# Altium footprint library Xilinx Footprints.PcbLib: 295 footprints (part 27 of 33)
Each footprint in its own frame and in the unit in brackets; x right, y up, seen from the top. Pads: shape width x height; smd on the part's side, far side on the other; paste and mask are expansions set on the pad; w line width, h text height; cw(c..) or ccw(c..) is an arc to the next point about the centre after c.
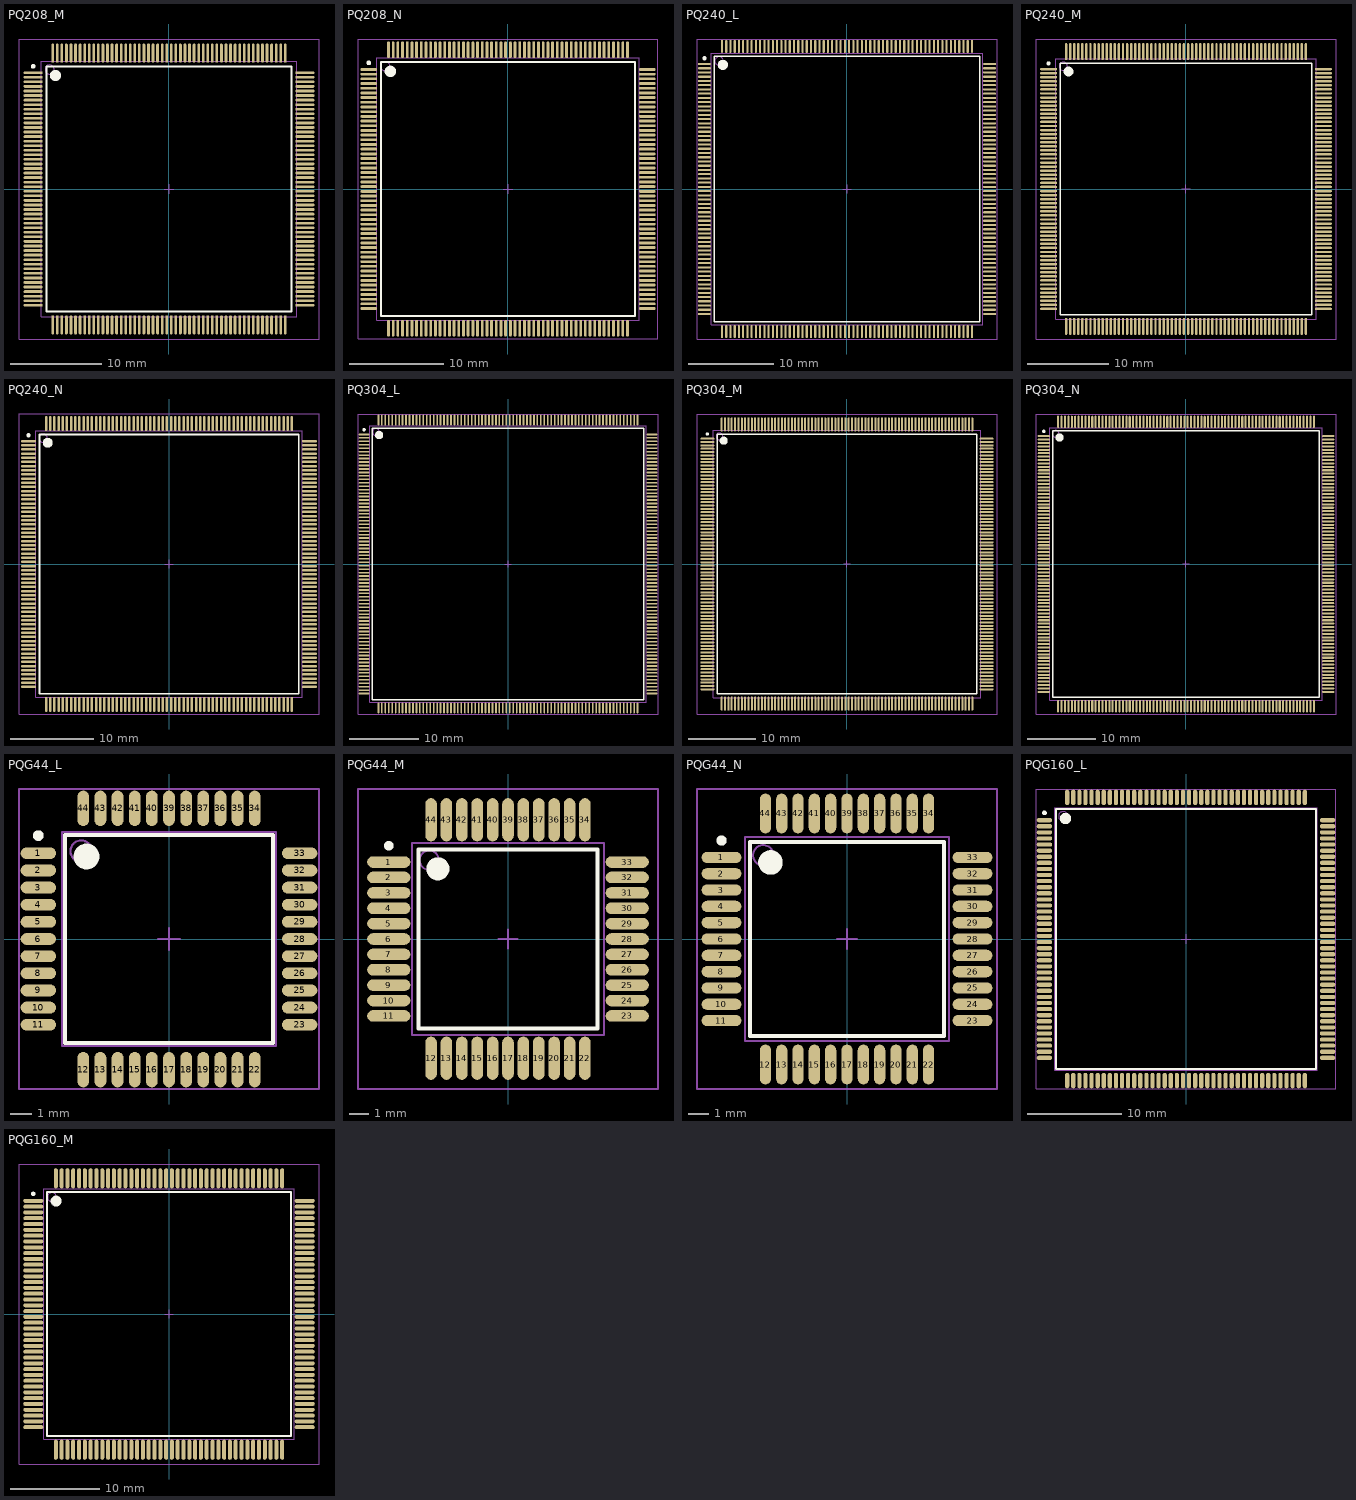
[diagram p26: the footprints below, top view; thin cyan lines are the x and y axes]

## PQ208_M [mm] "208-Pin Plastic Quad Flat Pack (PQ208), IPC Low Density"
height 4.1
pads (208):
  oval 2.1x0.3 smd: 1(-14.9,12.75) 2(-14.9,12.25) 3(-14.9,11.75) 4(-14.9,11.25) 5(-14.9,10.75) 6(-14.9,10.25) 7(-14.9,9.75) 8(-14.9,9.25) 9(-14.9,8.75) 10(-14.9,8.25) 11(-14.9,7.75) 12(-14.9,7.25) 13(-14.9,6.75) 14(-14.9,6.25) 15(-14.9,5.75) 16(-14.9,5.25) 17(-14.9,4.75) 18(-14.9,4.25) 19(-14.9,3.75) 20(-14.9,3.25) 21(-14.9,2.75) 22(-14.9,2.25) 23(-14.9,1.75) 24(-14.9,1.25) 25(-14.9,0.75) 26(-14.9,0.25) 27(-14.9,-0.25) 28(-14.9,-0.75) 29(-14.9,-1.25) 30(-14.9,-1.75) 31(-14.9,-2.25) 32(-14.9,-2.75) 33(-14.9,-3.25) 34(-14.9,-3.75) 35(-14.9,-4.25) 36(-14.9,-4.75) 37(-14.9,-5.25) 38(-14.9,-5.75) 39(-14.9,-6.25) 40(-14.9,-6.75) 41(-14.9,-7.25) 42(-14.9,-7.75) 43(-14.9,-8.25) 44(-14.9,-8.75) 45(-14.9,-9.25) 46(-14.9,-9.75) 47(-14.9,-10.25) 48(-14.9,-10.75) 49(-14.9,-11.25) 50(-14.9,-11.75) 51(-14.9,-12.25) 52(-14.9,-12.75) 105(14.9,-12.75) 106(14.9,-12.25) 107(14.9,-11.75) 108(14.9,-11.25) 109(14.9,-10.75) 110(14.9,-10.25) 111(14.9,-9.75) 112(14.9,-9.25) 113(14.9,-8.75) 114(14.9,-8.25) 115(14.9,-7.75) 116(14.9,-7.25) 117(14.9,-6.75) 118(14.9,-6.25) 119(14.9,-5.75) 120(14.9,-5.25) 121(14.9,-4.75) 122(14.9,-4.25) 123(14.9,-3.75) 124(14.9,-3.25) 125(14.9,-2.75) 126(14.9,-2.25) 127(14.9,-1.75) 128(14.9,-1.25) 129(14.9,-0.75) 130(14.9,-0.25) 131(14.9,0.25) 132(14.9,0.75) 133(14.9,1.25) 134(14.9,1.75) 135(14.9,2.25) 136(14.9,2.75) 137(14.9,3.25) 138(14.9,3.75) 139(14.9,4.25) 140(14.9,4.75) 141(14.9,5.25) 142(14.9,5.75) 143(14.9,6.25) 144(14.9,6.75) 145(14.9,7.25) 146(14.9,7.75) 147(14.9,8.25) 148(14.9,8.75) 149(14.9,9.25) 150(14.9,9.75) 151(14.9,10.25) 152(14.9,10.75) 153(14.9,11.25) 154(14.9,11.75) 155(14.9,12.25) 156(14.9,12.75)
  oval 0.3x2.1 smd: 53(-12.75,-14.9) 54(-12.25,-14.9) 55(-11.75,-14.9) 56(-11.25,-14.9) 57(-10.75,-14.9) 58(-10.25,-14.9) 59(-9.75,-14.9) 60(-9.25,-14.9) 61(-8.75,-14.9) 62(-8.25,-14.9) 63(-7.75,-14.9) 64(-7.25,-14.9) 65(-6.75,-14.9) 66(-6.25,-14.9) 67(-5.75,-14.9) 68(-5.25,-14.9) 69(-4.75,-14.9) 70(-4.25,-14.9) 71(-3.75,-14.9) 72(-3.25,-14.9) 73(-2.75,-14.9) 74(-2.25,-14.9) 75(-1.75,-14.9) 76(-1.25,-14.9) 77(-0.75,-14.9) 78(-0.25,-14.9) 79(0.25,-14.9) 80(0.75,-14.9) 81(1.25,-14.9) 82(1.75,-14.9) 83(2.25,-14.9) 84(2.75,-14.9) 85(3.25,-14.9) 86(3.75,-14.9) 87(4.25,-14.9) 88(4.75,-14.9) 89(5.25,-14.9) 90(5.75,-14.9) 91(6.25,-14.9) 92(6.75,-14.9) 93(7.25,-14.9) 94(7.75,-14.9) 95(8.25,-14.9) 96(8.75,-14.9) 97(9.25,-14.9) 98(9.75,-14.9) 99(10.25,-14.9) 100(10.75,-14.9) 101(11.25,-14.9) 102(11.75,-14.9) 103(12.25,-14.9) 104(12.75,-14.9) 157(12.75,14.9) 158(12.25,14.9) 159(11.75,14.9) 160(11.25,14.9) 161(10.75,14.9) 162(10.25,14.9) 163(9.75,14.9) 164(9.25,14.9) 165(8.75,14.9) 166(8.25,14.9) 167(7.75,14.9) 168(7.25,14.9) 169(6.75,14.9) 170(6.25,14.9) 171(5.75,14.9) 172(5.25,14.9) 173(4.75,14.9) 174(4.25,14.9) 175(3.75,14.9) 176(3.25,14.9) 177(2.75,14.9) 178(2.25,14.9) 179(1.75,14.9) 180(1.25,14.9) 181(0.75,14.9) 182(0.25,14.9) 183(-0.25,14.9) 184(-0.75,14.9) 185(-1.25,14.9) 186(-1.75,14.9) 187(-2.25,14.9) 188(-2.75,14.9) 189(-3.25,14.9) 190(-3.75,14.9) 191(-4.25,14.9) 192(-4.75,14.9) 193(-5.25,14.9) 194(-5.75,14.9) 195(-6.25,14.9) 196(-6.75,14.9) 197(-7.25,14.9) 198(-7.75,14.9) 199(-8.25,14.9) 200(-8.75,14.9) 201(-9.25,14.9) 202(-9.75,14.9) 203(-10.25,14.9) 204(-10.75,14.9) 205(-11.25,14.9) 206(-11.75,14.9) 207(-12.25,14.9) 208(-12.75,14.9)
Top Overlay:
  circle w0.6: c-12.45,12.45 r0.3
  circle w0.25: c-14.9,13.45 r0.125
  lines w0.2: -13.45,-13.45 13.45,-13.45 13.45,13.45 -13.45,13.45 -13.45,-13.45
Mechanical 13:
  circle w0.1: c-13.1,13.1 r0.5
  lines w0.1: -14,-14 14,-14 14,14 -14,14 -14,-14
Mechanical 15:
  lines w0.1: -0.5,0 0.5,0 ; 0,-0.5 0,0.5 ; -16.45,-16.45 16.45,-16.45 16.45,16.45 -16.45,16.45 -16.45,-16.45
3D body: height 4.1, standoff 0, extent -14,-14 14,14

## PQ208_N [mm] "208-Pin Plastic Quad Flat Pack (PQ208), IPC Medium Density"
height 4.1
pads (208):
  oval 1.8x0.3 smd: 1(-14.85,12.75) 2(-14.85,12.25) 3(-14.85,11.75) 4(-14.85,11.25) 5(-14.85,10.75) 6(-14.85,10.25) 7(-14.85,9.75) 8(-14.85,9.25) 9(-14.85,8.75) 10(-14.85,8.25) 11(-14.85,7.75) 12(-14.85,7.25) 13(-14.85,6.75) 14(-14.85,6.25) 15(-14.85,5.75) 16(-14.85,5.25) 17(-14.85,4.75) 18(-14.85,4.25) 19(-14.85,3.75) 20(-14.85,3.25) 21(-14.85,2.75) 22(-14.85,2.25) 23(-14.85,1.75) 24(-14.85,1.25) 25(-14.85,0.75) 26(-14.85,0.25) 27(-14.85,-0.25) 28(-14.85,-0.75) 29(-14.85,-1.25) 30(-14.85,-1.75) 31(-14.85,-2.25) 32(-14.85,-2.75) 33(-14.85,-3.25) 34(-14.85,-3.75) 35(-14.85,-4.25) 36(-14.85,-4.75) 37(-14.85,-5.25) 38(-14.85,-5.75) 39(-14.85,-6.25) 40(-14.85,-6.75) 41(-14.85,-7.25) 42(-14.85,-7.75) 43(-14.85,-8.25) 44(-14.85,-8.75) 45(-14.85,-9.25) 46(-14.85,-9.75) 47(-14.85,-10.25) 48(-14.85,-10.75) 49(-14.85,-11.25) 50(-14.85,-11.75) 51(-14.85,-12.25) 52(-14.85,-12.75) 105(14.85,-12.75) 106(14.85,-12.25) 107(14.85,-11.75) 108(14.85,-11.25) 109(14.85,-10.75) 110(14.85,-10.25) 111(14.85,-9.75) 112(14.85,-9.25) 113(14.85,-8.75) 114(14.85,-8.25) 115(14.85,-7.75) 116(14.85,-7.25) 117(14.85,-6.75) 118(14.85,-6.25) 119(14.85,-5.75) 120(14.85,-5.25) 121(14.85,-4.75) 122(14.85,-4.25) 123(14.85,-3.75) 124(14.85,-3.25) 125(14.85,-2.75) 126(14.85,-2.25) 127(14.85,-1.75) 128(14.85,-1.25) 129(14.85,-0.75) 130(14.85,-0.25) 131(14.85,0.25) 132(14.85,0.75) 133(14.85,1.25) 134(14.85,1.75) 135(14.85,2.25) 136(14.85,2.75) 137(14.85,3.25) 138(14.85,3.75) 139(14.85,4.25) 140(14.85,4.75) 141(14.85,5.25) 142(14.85,5.75) 143(14.85,6.25) 144(14.85,6.75) 145(14.85,7.25) 146(14.85,7.75) 147(14.85,8.25) 148(14.85,8.75) 149(14.85,9.25) 150(14.85,9.75) 151(14.85,10.25) 152(14.85,10.75) 153(14.85,11.25) 154(14.85,11.75) 155(14.85,12.25) 156(14.85,12.75)
  oval 0.3x1.8 smd: 53(-12.75,-14.85) 54(-12.25,-14.85) 55(-11.75,-14.85) 56(-11.25,-14.85) 57(-10.75,-14.85) 58(-10.25,-14.85) 59(-9.75,-14.85) 60(-9.25,-14.85) 61(-8.75,-14.85) 62(-8.25,-14.85) 63(-7.75,-14.85) 64(-7.25,-14.85) 65(-6.75,-14.85) 66(-6.25,-14.85) 67(-5.75,-14.85) 68(-5.25,-14.85) 69(-4.75,-14.85) 70(-4.25,-14.85) 71(-3.75,-14.85) 72(-3.25,-14.85) 73(-2.75,-14.85) 74(-2.25,-14.85) 75(-1.75,-14.85) 76(-1.25,-14.85) 77(-0.75,-14.85) 78(-0.25,-14.85) 79(0.25,-14.85) 80(0.75,-14.85) 81(1.25,-14.85) 82(1.75,-14.85) 83(2.25,-14.85) 84(2.75,-14.85) 85(3.25,-14.85) 86(3.75,-14.85) 87(4.25,-14.85) 88(4.75,-14.85) 89(5.25,-14.85) 90(5.75,-14.85) 91(6.25,-14.85) 92(6.75,-14.85) 93(7.25,-14.85) 94(7.75,-14.85) 95(8.25,-14.85) 96(8.75,-14.85) 97(9.25,-14.85) 98(9.75,-14.85) 99(10.25,-14.85) 100(10.75,-14.85) 101(11.25,-14.85) 102(11.75,-14.85) 103(12.25,-14.85) 104(12.75,-14.85) 157(12.75,14.85) 158(12.25,14.85) 159(11.75,14.85) 160(11.25,14.85) 161(10.75,14.85) 162(10.25,14.85) 163(9.75,14.85) 164(9.25,14.85) 165(8.75,14.85) 166(8.25,14.85) 167(7.75,14.85) 168(7.25,14.85) 169(6.75,14.85) 170(6.25,14.85) 171(5.75,14.85) 172(5.25,14.85) 173(4.75,14.85) 174(4.25,14.85) 175(3.75,14.85) 176(3.25,14.85) 177(2.75,14.85) 178(2.25,14.85) 179(1.75,14.85) 180(1.25,14.85) 181(0.75,14.85) 182(0.25,14.85) 183(-0.25,14.85) 184(-0.75,14.85) 185(-1.25,14.85) 186(-1.75,14.85) 187(-2.25,14.85) 188(-2.75,14.85) 189(-3.25,14.85) 190(-3.75,14.85) 191(-4.25,14.85) 192(-4.75,14.85) 193(-5.25,14.85) 194(-5.75,14.85) 195(-6.25,14.85) 196(-6.75,14.85) 197(-7.25,14.85) 198(-7.75,14.85) 199(-8.25,14.85) 200(-8.75,14.85) 201(-9.25,14.85) 202(-9.75,14.85) 203(-10.25,14.85) 204(-10.75,14.85) 205(-11.25,14.85) 206(-11.75,14.85) 207(-12.25,14.85) 208(-12.75,14.85)
Top Overlay:
  circle w0.6: c-12.55,12.55 r0.3
  circle w0.25: c-14.85,13.45 r0.125
  lines w0.2: -13.55,-13.55 13.55,-13.55 13.55,13.55 -13.55,13.55 -13.55,-13.55
Mechanical 13:
  circle w0.1: c-13.1,13.1 r0.5
  lines w0.1: -14,-14 14,-14 14,14 -14,14 -14,-14
Mechanical 15:
  lines w0.1: -0.5,0 0.5,0 ; 0,-0.5 0,0.5 ; -16,-16 16,-16 16,16 -16,16 -16,-16
3D body: height 4.1, standoff 0, extent -14,-14 14,14

## PQ240_L [mm] "240-Pin Plastic Quad Flat Pack (PQ240), IPC High Density"
height 4.1
pads (240):
  oval 1.55x0.25 smd: 1(-16.825,14.75) 2(-16.825,14.25) 3(-16.825,13.75) 4(-16.825,13.25) 5(-16.825,12.75) 6(-16.825,12.25) 7(-16.825,11.75) 8(-16.825,11.25) 9(-16.825,10.75) 10(-16.825,10.25) 11(-16.825,9.75) 12(-16.825,9.25) 13(-16.825,8.75) 14(-16.825,8.25) 15(-16.825,7.75) 16(-16.825,7.25) 17(-16.825,6.75) 18(-16.825,6.25) 19(-16.825,5.75) 20(-16.825,5.25) 21(-16.825,4.75) 22(-16.825,4.25) 23(-16.825,3.75) 24(-16.825,3.25) 25(-16.825,2.75) 26(-16.825,2.25) 27(-16.825,1.75) 28(-16.825,1.25) 29(-16.825,0.75) 30(-16.825,0.25) 31(-16.825,-0.25) 32(-16.825,-0.75) 33(-16.825,-1.25) 34(-16.825,-1.75) 35(-16.825,-2.25) 36(-16.825,-2.75) 37(-16.825,-3.25) 38(-16.825,-3.75) 39(-16.825,-4.25) 40(-16.825,-4.75) 41(-16.825,-5.25) 42(-16.825,-5.75) 43(-16.825,-6.25) 44(-16.825,-6.75) 45(-16.825,-7.25) 46(-16.825,-7.75) 47(-16.825,-8.25) 48(-16.825,-8.75) 49(-16.825,-9.25) 50(-16.825,-9.75) 51(-16.825,-10.25) 52(-16.825,-10.75) 53(-16.825,-11.25) 54(-16.825,-11.75) 55(-16.825,-12.25) 56(-16.825,-12.75) 57(-16.825,-13.25) 58(-16.825,-13.75) 59(-16.825,-14.25) 60(-16.825,-14.75) 121(16.825,-14.75) 122(16.825,-14.25) 123(16.825,-13.75) 124(16.825,-13.25) 125(16.825,-12.75) 126(16.825,-12.25) 127(16.825,-11.75) 128(16.825,-11.25) 129(16.825,-10.75) 130(16.825,-10.25) 131(16.825,-9.75) 132(16.825,-9.25) 133(16.825,-8.75) 134(16.825,-8.25) 135(16.825,-7.75) 136(16.825,-7.25) 137(16.825,-6.75) 138(16.825,-6.25) 139(16.825,-5.75) 140(16.825,-5.25) 141(16.825,-4.75) 142(16.825,-4.25) 143(16.825,-3.75) 144(16.825,-3.25) 145(16.825,-2.75) 146(16.825,-2.25) 147(16.825,-1.75) 148(16.825,-1.25) 149(16.825,-0.75) 150(16.825,-0.25) 151(16.825,0.25) 152(16.825,0.75) 153(16.825,1.25) 154(16.825,1.75) 155(16.825,2.25) 156(16.825,2.75) 157(16.825,3.25) 158(16.825,3.75) 159(16.825,4.25) 160(16.825,4.75) 161(16.825,5.25) 162(16.825,5.75) 163(16.825,6.25) 164(16.825,6.75) 165(16.825,7.25) 166(16.825,7.75) 167(16.825,8.25) 168(16.825,8.75) 169(16.825,9.25) 170(16.825,9.75) 171(16.825,10.25) 172(16.825,10.75) 173(16.825,11.25) 174(16.825,11.75) 175(16.825,12.25) 176(16.825,12.75) 177(16.825,13.25) 178(16.825,13.75) 179(16.825,14.25) 180(16.825,14.75)
  oval 0.25x1.55 smd: 61(-14.75,-16.825) 62(-14.25,-16.825) 63(-13.75,-16.825) 64(-13.25,-16.825) 65(-12.75,-16.825) 66(-12.25,-16.825) 67(-11.75,-16.825) 68(-11.25,-16.825) 69(-10.75,-16.825) 70(-10.25,-16.825) 71(-9.75,-16.825) 72(-9.25,-16.825) 73(-8.75,-16.825) 74(-8.25,-16.825) 75(-7.75,-16.825) 76(-7.25,-16.825) 77(-6.75,-16.825) 78(-6.25,-16.825) 79(-5.75,-16.825) 80(-5.25,-16.825) 81(-4.75,-16.825) 82(-4.25,-16.825) 83(-3.75,-16.825) 84(-3.25,-16.825) 85(-2.75,-16.825) 86(-2.25,-16.825) 87(-1.75,-16.825) 88(-1.25,-16.825) 89(-0.75,-16.825) 90(-0.25,-16.825) 91(0.25,-16.825) 92(0.75,-16.825) 93(1.25,-16.825) 94(1.75,-16.825) 95(2.25,-16.825) 96(2.75,-16.825) 97(3.25,-16.825) 98(3.75,-16.825) 99(4.25,-16.825) 100(4.75,-16.825) 101(5.25,-16.825) 102(5.75,-16.825) 103(6.25,-16.825) 104(6.75,-16.825) 105(7.25,-16.825) 106(7.75,-16.825) 107(8.25,-16.825) 108(8.75,-16.825) 109(9.25,-16.825) 110(9.75,-16.825) 111(10.25,-16.825) 112(10.75,-16.825) 113(11.25,-16.825) 114(11.75,-16.825) 115(12.25,-16.825) 116(12.75,-16.825) 117(13.25,-16.825) 118(13.75,-16.825) 119(14.25,-16.825) 120(14.75,-16.825) 181(14.75,16.825) 182(14.25,16.825) 183(13.75,16.825) 184(13.25,16.825) 185(12.75,16.825) 186(12.25,16.825) 187(11.75,16.825) 188(11.25,16.825) 189(10.75,16.825) 190(10.25,16.825) 191(9.75,16.825) 192(9.25,16.825) 193(8.75,16.825) 194(8.25,16.825) 195(7.75,16.825) 196(7.25,16.825) 197(6.75,16.825) 198(6.25,16.825) 199(5.75,16.825) 200(5.25,16.825) 201(4.75,16.825) 202(4.25,16.825) 203(3.75,16.825) 204(3.25,16.825) 205(2.75,16.825) 206(2.25,16.825) 207(1.75,16.825) 208(1.25,16.825) 209(0.75,16.825) 210(0.25,16.825) 211(-0.25,16.825) 212(-0.75,16.825) 213(-1.25,16.825) 214(-1.75,16.825) 215(-2.25,16.825) 216(-2.75,16.825) 217(-3.25,16.825) 218(-3.75,16.825) 219(-4.25,16.825) 220(-4.75,16.825) 221(-5.25,16.825) 222(-5.75,16.825) 223(-6.25,16.825) 224(-6.75,16.825) 225(-7.25,16.825) 226(-7.75,16.825) 227(-8.25,16.825) 228(-8.75,16.825) 229(-9.25,16.825) 230(-9.75,16.825) 231(-10.25,16.825) 232(-10.75,16.825) 233(-11.25,16.825) 234(-11.75,16.825) 235(-12.25,16.825) 236(-12.75,16.825) 237(-13.25,16.825) 238(-13.75,16.825) 239(-14.25,16.825) 240(-14.75,16.825)
Top Overlay:
  circle w0.6: c-14.65,14.65 r0.3
  circle w0.25: c-16.825,15.425 r0.125
  lines w0.2: -15.65,-15.65 15.65,-15.65 15.65,15.65 -15.65,15.65 -15.65,-15.65
Mechanical 13:
  circle w0.1: c-15.1,15.1 r0.5
  lines w0.1: -16,-16 16,-16 16,16 -16,16 -16,-16
Mechanical 15:
  lines w0.1: -0.5,0 0.5,0 ; 0,-0.5 0,0.5 ; -17.7,-17.7 17.7,-17.7 17.7,17.7 -17.7,17.7 -17.7,-17.7
3D body: height 4.1, standoff 0, extent -16,-16 16,16

## PQ240_M [mm] "240-Pin Plastic Quad Flat Pack (PQ240), IPC Low Density"
height 4.1
pads (240):
  oval 2.1x0.3 smd: 1(-16.9,14.75) 2(-16.9,14.25) 3(-16.9,13.75) 4(-16.9,13.25) 5(-16.9,12.75) 6(-16.9,12.25) 7(-16.9,11.75) 8(-16.9,11.25) 9(-16.9,10.75) 10(-16.9,10.25) 11(-16.9,9.75) 12(-16.9,9.25) 13(-16.9,8.75) 14(-16.9,8.25) 15(-16.9,7.75) 16(-16.9,7.25) 17(-16.9,6.75) 18(-16.9,6.25) 19(-16.9,5.75) 20(-16.9,5.25) 21(-16.9,4.75) 22(-16.9,4.25) 23(-16.9,3.75) 24(-16.9,3.25) 25(-16.9,2.75) 26(-16.9,2.25) 27(-16.9,1.75) 28(-16.9,1.25) 29(-16.9,0.75) 30(-16.9,0.25) 31(-16.9,-0.25) 32(-16.9,-0.75) 33(-16.9,-1.25) 34(-16.9,-1.75) 35(-16.9,-2.25) 36(-16.9,-2.75) 37(-16.9,-3.25) 38(-16.9,-3.75) 39(-16.9,-4.25) 40(-16.9,-4.75) 41(-16.9,-5.25) 42(-16.9,-5.75) 43(-16.9,-6.25) 44(-16.9,-6.75) 45(-16.9,-7.25) 46(-16.9,-7.75) 47(-16.9,-8.25) 48(-16.9,-8.75) 49(-16.9,-9.25) 50(-16.9,-9.75) 51(-16.9,-10.25) 52(-16.9,-10.75) 53(-16.9,-11.25) 54(-16.9,-11.75) 55(-16.9,-12.25) 56(-16.9,-12.75) 57(-16.9,-13.25) 58(-16.9,-13.75) 59(-16.9,-14.25) 60(-16.9,-14.75) 121(16.9,-14.75) 122(16.9,-14.25) 123(16.9,-13.75) 124(16.9,-13.25) 125(16.9,-12.75) 126(16.9,-12.25) 127(16.9,-11.75) 128(16.9,-11.25) 129(16.9,-10.75) 130(16.9,-10.25) 131(16.9,-9.75) 132(16.9,-9.25) 133(16.9,-8.75) 134(16.9,-8.25) 135(16.9,-7.75) 136(16.9,-7.25) 137(16.9,-6.75) 138(16.9,-6.25) 139(16.9,-5.75) 140(16.9,-5.25) 141(16.9,-4.75) 142(16.9,-4.25) 143(16.9,-3.75) 144(16.9,-3.25) 145(16.9,-2.75) 146(16.9,-2.25) 147(16.9,-1.75) 148(16.9,-1.25) 149(16.9,-0.75) 150(16.9,-0.25) 151(16.9,0.25) 152(16.9,0.75) 153(16.9,1.25) 154(16.9,1.75) 155(16.9,2.25) 156(16.9,2.75) 157(16.9,3.25) 158(16.9,3.75) 159(16.9,4.25) 160(16.9,4.75) 161(16.9,5.25) 162(16.9,5.75) 163(16.9,6.25) 164(16.9,6.75) 165(16.9,7.25) 166(16.9,7.75) 167(16.9,8.25) 168(16.9,8.75) 169(16.9,9.25) 170(16.9,9.75) 171(16.9,10.25) 172(16.9,10.75) 173(16.9,11.25) 174(16.9,11.75) 175(16.9,12.25) 176(16.9,12.75) 177(16.9,13.25) 178(16.9,13.75) 179(16.9,14.25) 180(16.9,14.75)
  oval 0.3x2.1 smd: 61(-14.75,-16.9) 62(-14.25,-16.9) 63(-13.75,-16.9) 64(-13.25,-16.9) 65(-12.75,-16.9) 66(-12.25,-16.9) 67(-11.75,-16.9) 68(-11.25,-16.9) 69(-10.75,-16.9) 70(-10.25,-16.9) 71(-9.75,-16.9) 72(-9.25,-16.9) 73(-8.75,-16.9) 74(-8.25,-16.9) 75(-7.75,-16.9) 76(-7.25,-16.9) 77(-6.75,-16.9) 78(-6.25,-16.9) 79(-5.75,-16.9) 80(-5.25,-16.9) 81(-4.75,-16.9) 82(-4.25,-16.9) 83(-3.75,-16.9) 84(-3.25,-16.9) 85(-2.75,-16.9) 86(-2.25,-16.9) 87(-1.75,-16.9) 88(-1.25,-16.9) 89(-0.75,-16.9) 90(-0.25,-16.9) 91(0.25,-16.9) 92(0.75,-16.9) 93(1.25,-16.9) 94(1.75,-16.9) 95(2.25,-16.9) 96(2.75,-16.9) 97(3.25,-16.9) 98(3.75,-16.9) 99(4.25,-16.9) 100(4.75,-16.9) 101(5.25,-16.9) 102(5.75,-16.9) 103(6.25,-16.9) 104(6.75,-16.9) 105(7.25,-16.9) 106(7.75,-16.9) 107(8.25,-16.9) 108(8.75,-16.9) 109(9.25,-16.9) 110(9.75,-16.9) 111(10.25,-16.9) 112(10.75,-16.9) 113(11.25,-16.9) 114(11.75,-16.9) 115(12.25,-16.9) 116(12.75,-16.9) 117(13.25,-16.9) 118(13.75,-16.9) 119(14.25,-16.9) 120(14.75,-16.9) 181(14.75,16.9) 182(14.25,16.9) 183(13.75,16.9) 184(13.25,16.9) 185(12.75,16.9) 186(12.25,16.9) 187(11.75,16.9) 188(11.25,16.9) 189(10.75,16.9) 190(10.25,16.9) 191(9.75,16.9) 192(9.25,16.9) 193(8.75,16.9) 194(8.25,16.9) 195(7.75,16.9) 196(7.25,16.9) 197(6.75,16.9) 198(6.25,16.9) 199(5.75,16.9) 200(5.25,16.9) 201(4.75,16.9) 202(4.25,16.9) 203(3.75,16.9) 204(3.25,16.9) 205(2.75,16.9) 206(2.25,16.9) 207(1.75,16.9) 208(1.25,16.9) 209(0.75,16.9) 210(0.25,16.9) 211(-0.25,16.9) 212(-0.75,16.9) 213(-1.25,16.9) 214(-1.75,16.9) 215(-2.25,16.9) 216(-2.75,16.9) 217(-3.25,16.9) 218(-3.75,16.9) 219(-4.25,16.9) 220(-4.75,16.9) 221(-5.25,16.9) 222(-5.75,16.9) 223(-6.25,16.9) 224(-6.75,16.9) 225(-7.25,16.9) 226(-7.75,16.9) 227(-8.25,16.9) 228(-8.75,16.9) 229(-9.25,16.9) 230(-9.75,16.9) 231(-10.25,16.9) 232(-10.75,16.9) 233(-11.25,16.9) 234(-11.75,16.9) 235(-12.25,16.9) 236(-12.75,16.9) 237(-13.25,16.9) 238(-13.75,16.9) 239(-14.25,16.9) 240(-14.75,16.9)
Top Overlay:
  circle w0.6: c-14.45,14.45 r0.3
  circle w0.25: c-16.9,15.45 r0.125
  lines w0.2: -15.45,-15.45 15.45,-15.45 15.45,15.45 -15.45,15.45 -15.45,-15.45
Mechanical 13:
  circle w0.1: c-15.1,15.1 r0.5
  lines w0.1: -16,-16 16,-16 16,16 -16,16 -16,-16
Mechanical 15:
  lines w0.1: -0.5,0 0.5,0 ; 0,-0.5 0,0.5 ; -18.45,-18.45 18.45,-18.45 18.45,18.45 -18.45,18.45 -18.45,-18.45
3D body: height 4.1, standoff 0, extent -16,-16 16,16

## PQ240_N [mm] "240-Pin Plastic Quad Flat Pack (PQ240), IPC Medium Density"
height 4.1
pads (240):
  oval 1.8x0.3 smd: 1(-16.85,14.75) 2(-16.85,14.25) 3(-16.85,13.75) 4(-16.85,13.25) 5(-16.85,12.75) 6(-16.85,12.25) 7(-16.85,11.75) 8(-16.85,11.25) 9(-16.85,10.75) 10(-16.85,10.25) 11(-16.85,9.75) 12(-16.85,9.25) 13(-16.85,8.75) 14(-16.85,8.25) 15(-16.85,7.75) 16(-16.85,7.25) 17(-16.85,6.75) 18(-16.85,6.25) 19(-16.85,5.75) 20(-16.85,5.25) 21(-16.85,4.75) 22(-16.85,4.25) 23(-16.85,3.75) 24(-16.85,3.25) 25(-16.85,2.75) 26(-16.85,2.25) 27(-16.85,1.75) 28(-16.85,1.25) 29(-16.85,0.75) 30(-16.85,0.25) 31(-16.85,-0.25) 32(-16.85,-0.75) 33(-16.85,-1.25) 34(-16.85,-1.75) 35(-16.85,-2.25) 36(-16.85,-2.75) 37(-16.85,-3.25) 38(-16.85,-3.75) 39(-16.85,-4.25) 40(-16.85,-4.75) 41(-16.85,-5.25) 42(-16.85,-5.75) 43(-16.85,-6.25) 44(-16.85,-6.75) 45(-16.85,-7.25) 46(-16.85,-7.75) 47(-16.85,-8.25) 48(-16.85,-8.75) 49(-16.85,-9.25) 50(-16.85,-9.75) 51(-16.85,-10.25) 52(-16.85,-10.75) 53(-16.85,-11.25) 54(-16.85,-11.75) 55(-16.85,-12.25) 56(-16.85,-12.75) 57(-16.85,-13.25) 58(-16.85,-13.75) 59(-16.85,-14.25) 60(-16.85,-14.75) 121(16.85,-14.75) 122(16.85,-14.25) 123(16.85,-13.75) 124(16.85,-13.25) 125(16.85,-12.75) 126(16.85,-12.25) 127(16.85,-11.75) 128(16.85,-11.25) 129(16.85,-10.75) 130(16.85,-10.25) 131(16.85,-9.75) 132(16.85,-9.25) 133(16.85,-8.75) 134(16.85,-8.25) 135(16.85,-7.75) 136(16.85,-7.25) 137(16.85,-6.75) 138(16.85,-6.25) 139(16.85,-5.75) 140(16.85,-5.25) 141(16.85,-4.75) 142(16.85,-4.25) 143(16.85,-3.75) 144(16.85,-3.25) 145(16.85,-2.75) 146(16.85,-2.25) 147(16.85,-1.75) 148(16.85,-1.25) 149(16.85,-0.75) 150(16.85,-0.25) 151(16.85,0.25) 152(16.85,0.75) 153(16.85,1.25) 154(16.85,1.75) 155(16.85,2.25) 156(16.85,2.75) 157(16.85,3.25) 158(16.85,3.75) 159(16.85,4.25) 160(16.85,4.75) 161(16.85,5.25) 162(16.85,5.75) 163(16.85,6.25) 164(16.85,6.75) 165(16.85,7.25) 166(16.85,7.75) 167(16.85,8.25) 168(16.85,8.75) 169(16.85,9.25) 170(16.85,9.75) 171(16.85,10.25) 172(16.85,10.75) 173(16.85,11.25) 174(16.85,11.75) 175(16.85,12.25) 176(16.85,12.75) 177(16.85,13.25) 178(16.85,13.75) 179(16.85,14.25) 180(16.85,14.75)
  oval 0.3x1.8 smd: 61(-14.75,-16.85) 62(-14.25,-16.85) 63(-13.75,-16.85) 64(-13.25,-16.85) 65(-12.75,-16.85) 66(-12.25,-16.85) 67(-11.75,-16.85) 68(-11.25,-16.85) 69(-10.75,-16.85) 70(-10.25,-16.85) 71(-9.75,-16.85) 72(-9.25,-16.85) 73(-8.75,-16.85) 74(-8.25,-16.85) 75(-7.75,-16.85) 76(-7.25,-16.85) 77(-6.75,-16.85) 78(-6.25,-16.85) 79(-5.75,-16.85) 80(-5.25,-16.85) 81(-4.75,-16.85) 82(-4.25,-16.85) 83(-3.75,-16.85) 84(-3.25,-16.85) 85(-2.75,-16.85) 86(-2.25,-16.85) 87(-1.75,-16.85) 88(-1.25,-16.85) 89(-0.75,-16.85) 90(-0.25,-16.85) 91(0.25,-16.85) 92(0.75,-16.85) 93(1.25,-16.85) 94(1.75,-16.85) 95(2.25,-16.85) 96(2.75,-16.85) 97(3.25,-16.85) 98(3.75,-16.85) 99(4.25,-16.85) 100(4.75,-16.85) 101(5.25,-16.85) 102(5.75,-16.85) 103(6.25,-16.85) 104(6.75,-16.85) 105(7.25,-16.85) 106(7.75,-16.85) 107(8.25,-16.85) 108(8.75,-16.85) 109(9.25,-16.85) 110(9.75,-16.85) 111(10.25,-16.85) 112(10.75,-16.85) 113(11.25,-16.85) 114(11.75,-16.85) 115(12.25,-16.85) 116(12.75,-16.85) 117(13.25,-16.85) 118(13.75,-16.85) 119(14.25,-16.85) 120(14.75,-16.85) 181(14.75,16.85) 182(14.25,16.85) 183(13.75,16.85) 184(13.25,16.85) 185(12.75,16.85) 186(12.25,16.85) 187(11.75,16.85) 188(11.25,16.85) 189(10.75,16.85) 190(10.25,16.85) 191(9.75,16.85) 192(9.25,16.85) 193(8.75,16.85) 194(8.25,16.85) 195(7.75,16.85) 196(7.25,16.85) 197(6.75,16.85) 198(6.25,16.85) 199(5.75,16.85) 200(5.25,16.85) 201(4.75,16.85) 202(4.25,16.85) 203(3.75,16.85) 204(3.25,16.85) 205(2.75,16.85) 206(2.25,16.85) 207(1.75,16.85) 208(1.25,16.85) 209(0.75,16.85) 210(0.25,16.85) 211(-0.25,16.85) 212(-0.75,16.85) 213(-1.25,16.85) 214(-1.75,16.85) 215(-2.25,16.85) 216(-2.75,16.85) 217(-3.25,16.85) 218(-3.75,16.85) 219(-4.25,16.85) 220(-4.75,16.85) 221(-5.25,16.85) 222(-5.75,16.85) 223(-6.25,16.85) 224(-6.75,16.85) 225(-7.25,16.85) 226(-7.75,16.85) 227(-8.25,16.85) 228(-8.75,16.85) 229(-9.25,16.85) 230(-9.75,16.85) 231(-10.25,16.85) 232(-10.75,16.85) 233(-11.25,16.85) 234(-11.75,16.85) 235(-12.25,16.85) 236(-12.75,16.85) 237(-13.25,16.85) 238(-13.75,16.85) 239(-14.25,16.85) 240(-14.75,16.85)
Top Overlay:
  circle w0.6: c-14.55,14.55 r0.3
  circle w0.25: c-16.85,15.45 r0.125
  lines w0.2: -15.55,-15.55 15.55,-15.55 15.55,15.55 -15.55,15.55 -15.55,-15.55
Mechanical 13:
  circle w0.1: c-15.1,15.1 r0.5
  lines w0.1: -16,-16 16,-16 16,16 -16,16 -16,-16
Mechanical 15:
  lines w0.1: -0.5,0 0.5,0 ; 0,-0.5 0,0.5 ; -18,-18 18,-18 18,18 -18,18 -18,-18
3D body: height 4.1, standoff 0, extent -16,-16 16,16

## PQ304_L [mm] "304-Pin Plastic Quad Flat Pack (PQ304), IPC High Density"
height 4.5
pads (304):
  oval 1.55x0.25 smd: 1(-20.825,18.75) 2(-20.825,18.25) 3(-20.825,17.75) 4(-20.825,17.25) 5(-20.825,16.75) 6(-20.825,16.25) 7(-20.825,15.75) 8(-20.825,15.25) 9(-20.825,14.75) 10(-20.825,14.25) 11(-20.825,13.75) 12(-20.825,13.25) 13(-20.825,12.75) 14(-20.825,12.25) 15(-20.825,11.75) 16(-20.825,11.25) 17(-20.825,10.75) 18(-20.825,10.25) 19(-20.825,9.75) 20(-20.825,9.25) 21(-20.825,8.75) 22(-20.825,8.25) 23(-20.825,7.75) 24(-20.825,7.25) 25(-20.825,6.75) 26(-20.825,6.25) 27(-20.825,5.75) 28(-20.825,5.25) 29(-20.825,4.75) 30(-20.825,4.25) 31(-20.825,3.75) 32(-20.825,3.25) 33(-20.825,2.75) 34(-20.825,2.25) 35(-20.825,1.75) 36(-20.825,1.25) 37(-20.825,0.75) 38(-20.825,0.25) 39(-20.825,-0.25) 40(-20.825,-0.75) 41(-20.825,-1.25) 42(-20.825,-1.75) 43(-20.825,-2.25) 44(-20.825,-2.75) 45(-20.825,-3.25) 46(-20.825,-3.75) 47(-20.825,-4.25) 48(-20.825,-4.75) 49(-20.825,-5.25) 50(-20.825,-5.75) 51(-20.825,-6.25) 52(-20.825,-6.75) 53(-20.825,-7.25) 54(-20.825,-7.75) 55(-20.825,-8.25) 56(-20.825,-8.75) 57(-20.825,-9.25) 58(-20.825,-9.75) 59(-20.825,-10.25) 60(-20.825,-10.75) 61(-20.825,-11.25) 62(-20.825,-11.75) 63(-20.825,-12.25) 64(-20.825,-12.75) 65(-20.825,-13.25) 66(-20.825,-13.75) 67(-20.825,-14.25) 68(-20.825,-14.75) 69(-20.825,-15.25) 70(-20.825,-15.75) 71(-20.825,-16.25) 72(-20.825,-16.75) 73(-20.825,-17.25) 74(-20.825,-17.75) 75(-20.825,-18.25) 76(-20.825,-18.75) 153(20.825,-18.75) 154(20.825,-18.25) 155(20.825,-17.75) 156(20.825,-17.25) 157(20.825,-16.75) 158(20.825,-16.25) 159(20.825,-15.75) 160(20.825,-15.25) 161(20.825,-14.75) 162(20.825,-14.25) 163(20.825,-13.75) 164(20.825,-13.25) 165(20.825,-12.75) 166(20.825,-12.25) 167(20.825,-11.75) 168(20.825,-11.25) 169(20.825,-10.75) 170(20.825,-10.25) 171(20.825,-9.75) 172(20.825,-9.25) 173(20.825,-8.75) 174(20.825,-8.25) 175(20.825,-7.75) 176(20.825,-7.25) 177(20.825,-6.75) 178(20.825,-6.25) 179(20.825,-5.75) 180(20.825,-5.25) 181(20.825,-4.75) 182(20.825,-4.25) 183(20.825,-3.75) 184(20.825,-3.25) 185(20.825,-2.75) 186(20.825,-2.25) 187(20.825,-1.75) 188(20.825,-1.25) 189(20.825,-0.75) 190(20.825,-0.25) 191(20.825,0.25) 192(20.825,0.75) 193(20.825,1.25) 194(20.825,1.75) 195(20.825,2.25) 196(20.825,2.75) 197(20.825,3.25) 198(20.825,3.75) 199(20.825,4.25) 200(20.825,4.75) 201(20.825,5.25) 202(20.825,5.75) 203(20.825,6.25) 204(20.825,6.75) 205(20.825,7.25) 206(20.825,7.75) 207(20.825,8.25) 208(20.825,8.75) 209(20.825,9.25) 210(20.825,9.75) 211(20.825,10.25) 212(20.825,10.75) 213(20.825,11.25) 214(20.825,11.75) 215(20.825,12.25) 216(20.825,12.75) 217(20.825,13.25) 218(20.825,13.75) 219(20.825,14.25) 220(20.825,14.75) 221(20.825,15.25) 222(20.825,15.75) 223(20.825,16.25) 224(20.825,16.75) 225(20.825,17.25) 226(20.825,17.75) 227(20.825,18.25) 228(20.825,18.75)
  oval 0.25x1.55 smd: 77(-18.75,-20.825) 78(-18.25,-20.825) 79(-17.75,-20.825) 80(-17.25,-20.825) 81(-16.75,-20.825) 82(-16.25,-20.825) 83(-15.75,-20.825) 84(-15.25,-20.825) 85(-14.75,-20.825) 86(-14.25,-20.825) 87(-13.75,-20.825) 88(-13.25,-20.825) 89(-12.75,-20.825) 90(-12.25,-20.825) 91(-11.75,-20.825) 92(-11.25,-20.825) 93(-10.75,-20.825) 94(-10.25,-20.825) 95(-9.75,-20.825) 96(-9.25,-20.825) 97(-8.75,-20.825) 98(-8.25,-20.825) 99(-7.75,-20.825) 100(-7.25,-20.825) 101(-6.75,-20.825) 102(-6.25,-20.825) 103(-5.75,-20.825) 104(-5.25,-20.825) 105(-4.75,-20.825) 106(-4.25,-20.825) 107(-3.75,-20.825) 108(-3.25,-20.825) 109(-2.75,-20.825) 110(-2.25,-20.825) 111(-1.75,-20.825) 112(-1.25,-20.825) 113(-0.75,-20.825) 114(-0.25,-20.825) 115(0.25,-20.825) 116(0.75,-20.825) 117(1.25,-20.825) 118(1.75,-20.825) 119(2.25,-20.825) 120(2.75,-20.825) 121(3.25,-20.825) 122(3.75,-20.825) 123(4.25,-20.825) 124(4.75,-20.825) 125(5.25,-20.825) 126(5.75,-20.825) 127(6.25,-20.825) 128(6.75,-20.825) 129(7.25,-20.825) 130(7.75,-20.825) 131(8.25,-20.825) 132(8.75,-20.825) 133(9.25,-20.825) 134(9.75,-20.825) 135(10.25,-20.825) 136(10.75,-20.825) 137(11.25,-20.825) 138(11.75,-20.825) 139(12.25,-20.825) 140(12.75,-20.825) 141(13.25,-20.825) 142(13.75,-20.825) 143(14.25,-20.825) 144(14.75,-20.825) 145(15.25,-20.825) 146(15.75,-20.825) 147(16.25,-20.825) 148(16.75,-20.825) 149(17.25,-20.825) 150(17.75,-20.825) 151(18.25,-20.825) 152(18.75,-20.825) 229(18.75,20.825) 230(18.25,20.825) 231(17.75,20.825) 232(17.25,20.825) 233(16.75,20.825) 234(16.25,20.825) 235(15.75,20.825) 236(15.25,20.825) 237(14.75,20.825) 238(14.25,20.825) 239(13.75,20.825) 240(13.25,20.825) 241(12.75,20.825) 242(12.25,20.825) 243(11.75,20.825) 244(11.25,20.825) 245(10.75,20.825) 246(10.25,20.825) 247(9.75,20.825) 248(9.25,20.825) 249(8.75,20.825) 250(8.25,20.825) 251(7.75,20.825) 252(7.25,20.825) 253(6.75,20.825) 254(6.25,20.825) 255(5.75,20.825) 256(5.25,20.825) 257(4.75,20.825) 258(4.25,20.825) 259(3.75,20.825) 260(3.25,20.825) 261(2.75,20.825) 262(2.25,20.825) 263(1.75,20.825) 264(1.25,20.825) 265(0.75,20.825) 266(0.25,20.825) 267(-0.25,20.825) 268(-0.75,20.825) 269(-1.25,20.825) 270(-1.75,20.825) 271(-2.25,20.825) 272(-2.75,20.825) 273(-3.25,20.825) 274(-3.75,20.825) 275(-4.25,20.825) 276(-4.75,20.825) 277(-5.25,20.825) 278(-5.75,20.825) 279(-6.25,20.825) 280(-6.75,20.825) 281(-7.25,20.825) 282(-7.75,20.825) 283(-8.25,20.825) 284(-8.75,20.825) 285(-9.25,20.825) 286(-9.75,20.825) 287(-10.25,20.825) 288(-10.75,20.825) 289(-11.25,20.825) 290(-11.75,20.825) 291(-12.25,20.825) 292(-12.75,20.825) 293(-13.25,20.825) 294(-13.75,20.825) 295(-14.25,20.825) 296(-14.75,20.825) 297(-15.25,20.825) 298(-15.75,20.825) 299(-16.25,20.825) 300(-16.75,20.825) 301(-17.25,20.825) 302(-17.75,20.825) 303(-18.25,20.825) 304(-18.75,20.825)
Top Overlay:
  circle w0.6: c-18.65,18.65 r0.3
  circle w0.25: c-20.825,19.425 r0.125
  lines w0.2: -19.65,-19.65 19.65,-19.65 19.65,19.65 -19.65,19.65 -19.65,-19.65
Mechanical 13:
  circle w0.1: c-19.1,19.1 r0.5
  lines w0.1: -20,-20 20,-20 20,20 -20,20 -20,-20
Mechanical 15:
  lines w0.1: -0.5,0 0.5,0 ; 0,-0.5 0,0.5 ; -21.7,-21.7 21.7,-21.7 21.7,21.7 -21.7,21.7 -21.7,-21.7
3D body: height 4.5, standoff 0, extent -20,-20 20,20

## PQ304_M [mm] "304-Pin Plastic Quad Flat Pack (PQ304), IPC Low Density"
height 4.5
pads (304):
  oval 2.1x0.3 smd: 1(-20.9,18.75) 2(-20.9,18.25) 3(-20.9,17.75) 4(-20.9,17.25) 5(-20.9,16.75) 6(-20.9,16.25) 7(-20.9,15.75) 8(-20.9,15.25) 9(-20.9,14.75) 10(-20.9,14.25) 11(-20.9,13.75) 12(-20.9,13.25) 13(-20.9,12.75) 14(-20.9,12.25) 15(-20.9,11.75) 16(-20.9,11.25) 17(-20.9,10.75) 18(-20.9,10.25) 19(-20.9,9.75) 20(-20.9,9.25) 21(-20.9,8.75) 22(-20.9,8.25) 23(-20.9,7.75) 24(-20.9,7.25) 25(-20.9,6.75) 26(-20.9,6.25) 27(-20.9,5.75) 28(-20.9,5.25) 29(-20.9,4.75) 30(-20.9,4.25) 31(-20.9,3.75) 32(-20.9,3.25) 33(-20.9,2.75) 34(-20.9,2.25) 35(-20.9,1.75) 36(-20.9,1.25) 37(-20.9,0.75) 38(-20.9,0.25) 39(-20.9,-0.25) 40(-20.9,-0.75) 41(-20.9,-1.25) 42(-20.9,-1.75) 43(-20.9,-2.25) 44(-20.9,-2.75) 45(-20.9,-3.25) 46(-20.9,-3.75) 47(-20.9,-4.25) 48(-20.9,-4.75) 49(-20.9,-5.25) 50(-20.9,-5.75) 51(-20.9,-6.25) 52(-20.9,-6.75) 53(-20.9,-7.25) 54(-20.9,-7.75) 55(-20.9,-8.25) 56(-20.9,-8.75) 57(-20.9,-9.25) 58(-20.9,-9.75) 59(-20.9,-10.25) 60(-20.9,-10.75) 61(-20.9,-11.25) 62(-20.9,-11.75) 63(-20.9,-12.25) 64(-20.9,-12.75) 65(-20.9,-13.25) 66(-20.9,-13.75) 67(-20.9,-14.25) 68(-20.9,-14.75) 69(-20.9,-15.25) 70(-20.9,-15.75) 71(-20.9,-16.25) 72(-20.9,-16.75) 73(-20.9,-17.25) 74(-20.9,-17.75) 75(-20.9,-18.25) 76(-20.9,-18.75) 153(20.9,-18.75) 154(20.9,-18.25) 155(20.9,-17.75) 156(20.9,-17.25) 157(20.9,-16.75) 158(20.9,-16.25) 159(20.9,-15.75) 160(20.9,-15.25) 161(20.9,-14.75) 162(20.9,-14.25) 163(20.9,-13.75) 164(20.9,-13.25) 165(20.9,-12.75) 166(20.9,-12.25) 167(20.9,-11.75) 168(20.9,-11.25) 169(20.9,-10.75) 170(20.9,-10.25) 171(20.9,-9.75) 172(20.9,-9.25) 173(20.9,-8.75) 174(20.9,-8.25) 175(20.9,-7.75) 176(20.9,-7.25) 177(20.9,-6.75) 178(20.9,-6.25) 179(20.9,-5.75) 180(20.9,-5.25) 181(20.9,-4.75) 182(20.9,-4.25) 183(20.9,-3.75) 184(20.9,-3.25) 185(20.9,-2.75) 186(20.9,-2.25) 187(20.9,-1.75) 188(20.9,-1.25) 189(20.9,-0.75) 190(20.9,-0.25) 191(20.9,0.25) 192(20.9,0.75) 193(20.9,1.25) 194(20.9,1.75) 195(20.9,2.25) 196(20.9,2.75) 197(20.9,3.25) 198(20.9,3.75) 199(20.9,4.25) 200(20.9,4.75) 201(20.9,5.25) 202(20.9,5.75) 203(20.9,6.25) 204(20.9,6.75) 205(20.9,7.25) 206(20.9,7.75) 207(20.9,8.25) 208(20.9,8.75) 209(20.9,9.25) 210(20.9,9.75) 211(20.9,10.25) 212(20.9,10.75) 213(20.9,11.25) 214(20.9,11.75) 215(20.9,12.25) 216(20.9,12.75) 217(20.9,13.25) 218(20.9,13.75) 219(20.9,14.25) 220(20.9,14.75) 221(20.9,15.25) 222(20.9,15.75) 223(20.9,16.25) 224(20.9,16.75) 225(20.9,17.25) 226(20.9,17.75) 227(20.9,18.25) 228(20.9,18.75)
  oval 0.3x2.1 smd: 77(-18.75,-20.9) 78(-18.25,-20.9) 79(-17.75,-20.9) 80(-17.25,-20.9) 81(-16.75,-20.9) 82(-16.25,-20.9) 83(-15.75,-20.9) 84(-15.25,-20.9) 85(-14.75,-20.9) 86(-14.25,-20.9) 87(-13.75,-20.9) 88(-13.25,-20.9) 89(-12.75,-20.9) 90(-12.25,-20.9) 91(-11.75,-20.9) 92(-11.25,-20.9) 93(-10.75,-20.9) 94(-10.25,-20.9) 95(-9.75,-20.9) 96(-9.25,-20.9) 97(-8.75,-20.9) 98(-8.25,-20.9) 99(-7.75,-20.9) 100(-7.25,-20.9) 101(-6.75,-20.9) 102(-6.25,-20.9) 103(-5.75,-20.9) 104(-5.25,-20.9) 105(-4.75,-20.9) 106(-4.25,-20.9) 107(-3.75,-20.9) 108(-3.25,-20.9) 109(-2.75,-20.9) 110(-2.25,-20.9) 111(-1.75,-20.9) 112(-1.25,-20.9) 113(-0.75,-20.9) 114(-0.25,-20.9) 115(0.25,-20.9) 116(0.75,-20.9) 117(1.25,-20.9) 118(1.75,-20.9) 119(2.25,-20.9) 120(2.75,-20.9) 121(3.25,-20.9) 122(3.75,-20.9) 123(4.25,-20.9) 124(4.75,-20.9) 125(5.25,-20.9) 126(5.75,-20.9) 127(6.25,-20.9) 128(6.75,-20.9) 129(7.25,-20.9) 130(7.75,-20.9) 131(8.25,-20.9) 132(8.75,-20.9) 133(9.25,-20.9) 134(9.75,-20.9) 135(10.25,-20.9) 136(10.75,-20.9) 137(11.25,-20.9) 138(11.75,-20.9) 139(12.25,-20.9) 140(12.75,-20.9) 141(13.25,-20.9) 142(13.75,-20.9) 143(14.25,-20.9) 144(14.75,-20.9) 145(15.25,-20.9) 146(15.75,-20.9) 147(16.25,-20.9) 148(16.75,-20.9) 149(17.25,-20.9) 150(17.75,-20.9) 151(18.25,-20.9) 152(18.75,-20.9) 229(18.75,20.9) 230(18.25,20.9) 231(17.75,20.9) 232(17.25,20.9) 233(16.75,20.9) 234(16.25,20.9) 235(15.75,20.9) 236(15.25,20.9) 237(14.75,20.9) 238(14.25,20.9) 239(13.75,20.9) 240(13.25,20.9) 241(12.75,20.9) 242(12.25,20.9) 243(11.75,20.9) 244(11.25,20.9) 245(10.75,20.9) 246(10.25,20.9) 247(9.75,20.9) 248(9.25,20.9) 249(8.75,20.9) 250(8.25,20.9) 251(7.75,20.9) 252(7.25,20.9) 253(6.75,20.9) 254(6.25,20.9) 255(5.75,20.9) 256(5.25,20.9) 257(4.75,20.9) 258(4.25,20.9) 259(3.75,20.9) 260(3.25,20.9) 261(2.75,20.9) 262(2.25,20.9) 263(1.75,20.9) 264(1.25,20.9) 265(0.75,20.9) 266(0.25,20.9) 267(-0.25,20.9) 268(-0.75,20.9) 269(-1.25,20.9) 270(-1.75,20.9) 271(-2.25,20.9) 272(-2.75,20.9) 273(-3.25,20.9) 274(-3.75,20.9) 275(-4.25,20.9) 276(-4.75,20.9) 277(-5.25,20.9) 278(-5.75,20.9) 279(-6.25,20.9) 280(-6.75,20.9) 281(-7.25,20.9) 282(-7.75,20.9) 283(-8.25,20.9) 284(-8.75,20.9) 285(-9.25,20.9) 286(-9.75,20.9) 287(-10.25,20.9) 288(-10.75,20.9) 289(-11.25,20.9) 290(-11.75,20.9) 291(-12.25,20.9) 292(-12.75,20.9) 293(-13.25,20.9) 294(-13.75,20.9) 295(-14.25,20.9) 296(-14.75,20.9) 297(-15.25,20.9) 298(-15.75,20.9) 299(-16.25,20.9) 300(-16.75,20.9) 301(-17.25,20.9) 302(-17.75,20.9) 303(-18.25,20.9) 304(-18.75,20.9)
Top Overlay:
  circle w0.6: c-18.45,18.45 r0.3
  circle w0.25: c-20.9,19.45 r0.125
  lines w0.2: -19.45,-19.45 19.45,-19.45 19.45,19.45 -19.45,19.45 -19.45,-19.45
Mechanical 13:
  circle w0.1: c-19.1,19.1 r0.5
  lines w0.1: -20,-20 20,-20 20,20 -20,20 -20,-20
Mechanical 15:
  lines w0.1: -0.5,0 0.5,0 ; 0,-0.5 0,0.5 ; -22.45,-22.45 22.45,-22.45 22.45,22.45 -22.45,22.45 -22.45,-22.45
3D body: height 4.5, standoff 0, extent -20,-20 20,20

## PQ304_N [mm] "304-Pin Plastic Quad Flat Pack (PQ304), IPC Medium Density"
height 4.5
pads (304):
  oval 1.8x0.3 smd: 1(-20.85,18.75) 2(-20.85,18.25) 3(-20.85,17.75) 4(-20.85,17.25) 5(-20.85,16.75) 6(-20.85,16.25) 7(-20.85,15.75) 8(-20.85,15.25) 9(-20.85,14.75) 10(-20.85,14.25) 11(-20.85,13.75) 12(-20.85,13.25) 13(-20.85,12.75) 14(-20.85,12.25) 15(-20.85,11.75) 16(-20.85,11.25) 17(-20.85,10.75) 18(-20.85,10.25) 19(-20.85,9.75) 20(-20.85,9.25) 21(-20.85,8.75) 22(-20.85,8.25) 23(-20.85,7.75) 24(-20.85,7.25) 25(-20.85,6.75) 26(-20.85,6.25) 27(-20.85,5.75) 28(-20.85,5.25) 29(-20.85,4.75) 30(-20.85,4.25) 31(-20.85,3.75) 32(-20.85,3.25) 33(-20.85,2.75) 34(-20.85,2.25) 35(-20.85,1.75) 36(-20.85,1.25) 37(-20.85,0.75) 38(-20.85,0.25) 39(-20.85,-0.25) 40(-20.85,-0.75) 41(-20.85,-1.25) 42(-20.85,-1.75) 43(-20.85,-2.25) 44(-20.85,-2.75) 45(-20.85,-3.25) 46(-20.85,-3.75) 47(-20.85,-4.25) 48(-20.85,-4.75) 49(-20.85,-5.25) 50(-20.85,-5.75) 51(-20.85,-6.25) 52(-20.85,-6.75) 53(-20.85,-7.25) 54(-20.85,-7.75) 55(-20.85,-8.25) 56(-20.85,-8.75) 57(-20.85,-9.25) 58(-20.85,-9.75) 59(-20.85,-10.25) 60(-20.85,-10.75) 61(-20.85,-11.25) 62(-20.85,-11.75) 63(-20.85,-12.25) 64(-20.85,-12.75) 65(-20.85,-13.25) 66(-20.85,-13.75) 67(-20.85,-14.25) 68(-20.85,-14.75) 69(-20.85,-15.25) 70(-20.85,-15.75) 71(-20.85,-16.25) 72(-20.85,-16.75) 73(-20.85,-17.25) 74(-20.85,-17.75) 75(-20.85,-18.25) 76(-20.85,-18.75) 153(20.85,-18.75) 154(20.85,-18.25) 155(20.85,-17.75) 156(20.85,-17.25) 157(20.85,-16.75) 158(20.85,-16.25) 159(20.85,-15.75) 160(20.85,-15.25) 161(20.85,-14.75) 162(20.85,-14.25) 163(20.85,-13.75) 164(20.85,-13.25) 165(20.85,-12.75) 166(20.85,-12.25) 167(20.85,-11.75) 168(20.85,-11.25) 169(20.85,-10.75) 170(20.85,-10.25) 171(20.85,-9.75) 172(20.85,-9.25) 173(20.85,-8.75) 174(20.85,-8.25) 175(20.85,-7.75) 176(20.85,-7.25) 177(20.85,-6.75) 178(20.85,-6.25) 179(20.85,-5.75) 180(20.85,-5.25) 181(20.85,-4.75) 182(20.85,-4.25) 183(20.85,-3.75) 184(20.85,-3.25) 185(20.85,-2.75) 186(20.85,-2.25) 187(20.85,-1.75) 188(20.85,-1.25) 189(20.85,-0.75) 190(20.85,-0.25) 191(20.85,0.25) 192(20.85,0.75) 193(20.85,1.25) 194(20.85,1.75) 195(20.85,2.25) 196(20.85,2.75) 197(20.85,3.25) 198(20.85,3.75) 199(20.85,4.25) 200(20.85,4.75) 201(20.85,5.25) 202(20.85,5.75) 203(20.85,6.25) 204(20.85,6.75) 205(20.85,7.25) 206(20.85,7.75) 207(20.85,8.25) 208(20.85,8.75) 209(20.85,9.25) 210(20.85,9.75) 211(20.85,10.25) 212(20.85,10.75) 213(20.85,11.25) 214(20.85,11.75) 215(20.85,12.25) 216(20.85,12.75) 217(20.85,13.25) 218(20.85,13.75) 219(20.85,14.25) 220(20.85,14.75) 221(20.85,15.25) 222(20.85,15.75) 223(20.85,16.25) 224(20.85,16.75) 225(20.85,17.25) 226(20.85,17.75) 227(20.85,18.25) 228(20.85,18.75)
  oval 0.3x1.8 smd: 77(-18.75,-20.85) 78(-18.25,-20.85) 79(-17.75,-20.85) 80(-17.25,-20.85) 81(-16.75,-20.85) 82(-16.25,-20.85) 83(-15.75,-20.85) 84(-15.25,-20.85) 85(-14.75,-20.85) 86(-14.25,-20.85) 87(-13.75,-20.85) 88(-13.25,-20.85) 89(-12.75,-20.85) 90(-12.25,-20.85) 91(-11.75,-20.85) 92(-11.25,-20.85) 93(-10.75,-20.85) 94(-10.25,-20.85) 95(-9.75,-20.85) 96(-9.25,-20.85) 97(-8.75,-20.85) 98(-8.25,-20.85) 99(-7.75,-20.85) 100(-7.25,-20.85) 101(-6.75,-20.85) 102(-6.25,-20.85) 103(-5.75,-20.85) 104(-5.25,-20.85) 105(-4.75,-20.85) 106(-4.25,-20.85) 107(-3.75,-20.85) 108(-3.25,-20.85) 109(-2.75,-20.85) 110(-2.25,-20.85) 111(-1.75,-20.85) 112(-1.25,-20.85) 113(-0.75,-20.85) 114(-0.25,-20.85) 115(0.25,-20.85) 116(0.75,-20.85) 117(1.25,-20.85) 118(1.75,-20.85) 119(2.25,-20.85) 120(2.75,-20.85) 121(3.25,-20.85) 122(3.75,-20.85) 123(4.25,-20.85) 124(4.75,-20.85) 125(5.25,-20.85) 126(5.75,-20.85) 127(6.25,-20.85) 128(6.75,-20.85) 129(7.25,-20.85) 130(7.75,-20.85) 131(8.25,-20.85) 132(8.75,-20.85) 133(9.25,-20.85) 134(9.75,-20.85) 135(10.25,-20.85) 136(10.75,-20.85) 137(11.25,-20.85) 138(11.75,-20.85) 139(12.25,-20.85) 140(12.75,-20.85) 141(13.25,-20.85) 142(13.75,-20.85) 143(14.25,-20.85) 144(14.75,-20.85) 145(15.25,-20.85) 146(15.75,-20.85) 147(16.25,-20.85) 148(16.75,-20.85) 149(17.25,-20.85) 150(17.75,-20.85) 151(18.25,-20.85) 152(18.75,-20.85) 229(18.75,20.85) 230(18.25,20.85) 231(17.75,20.85) 232(17.25,20.85) 233(16.75,20.85) 234(16.25,20.85) 235(15.75,20.85) 236(15.25,20.85) 237(14.75,20.85) 238(14.25,20.85) 239(13.75,20.85) 240(13.25,20.85) 241(12.75,20.85) 242(12.25,20.85) 243(11.75,20.85) 244(11.25,20.85) 245(10.75,20.85) 246(10.25,20.85) 247(9.75,20.85) 248(9.25,20.85) 249(8.75,20.85) 250(8.25,20.85) 251(7.75,20.85) 252(7.25,20.85) 253(6.75,20.85) 254(6.25,20.85) 255(5.75,20.85) 256(5.25,20.85) 257(4.75,20.85) 258(4.25,20.85) 259(3.75,20.85) 260(3.25,20.85) 261(2.75,20.85) 262(2.25,20.85) 263(1.75,20.85) 264(1.25,20.85) 265(0.75,20.85) 266(0.25,20.85) 267(-0.25,20.85) 268(-0.75,20.85) 269(-1.25,20.85) 270(-1.75,20.85) 271(-2.25,20.85) 272(-2.75,20.85) 273(-3.25,20.85) 274(-3.75,20.85) 275(-4.25,20.85) 276(-4.75,20.85) 277(-5.25,20.85) 278(-5.75,20.85) 279(-6.25,20.85) 280(-6.75,20.85) 281(-7.25,20.85) 282(-7.75,20.85) 283(-8.25,20.85) 284(-8.75,20.85) 285(-9.25,20.85) 286(-9.75,20.85) 287(-10.25,20.85) 288(-10.75,20.85) 289(-11.25,20.85) 290(-11.75,20.85) 291(-12.25,20.85) 292(-12.75,20.85) 293(-13.25,20.85) 294(-13.75,20.85) 295(-14.25,20.85) 296(-14.75,20.85) 297(-15.25,20.85) 298(-15.75,20.85) 299(-16.25,20.85) 300(-16.75,20.85) 301(-17.25,20.85) 302(-17.75,20.85) 303(-18.25,20.85) 304(-18.75,20.85)
Top Overlay:
  circle w0.6: c-18.55,18.55 r0.3
  circle w0.25: c-20.85,19.45 r0.125
  lines w0.2: -19.55,-19.55 19.55,-19.55 19.55,19.55 -19.55,19.55 -19.55,-19.55
Mechanical 13:
  circle w0.1: c-19.1,19.1 r0.5
  lines w0.1: -20,-20 20,-20 20,20 -20,20 -20,-20
Mechanical 15:
  lines w0.1: -0.5,0 0.5,0 ; 0,-0.5 0,0.5 ; -22,-22 22,-22 22,22 -22,22 -22,-22
3D body: height 4.5, standoff 0, extent -20,-20 20,20

## PQG44_L [mm] "44-Pin Plastic Quad Flat Pack (PQG44) - Pb-Free, IPC High Density"
height 2.35
pads (44):
  oval 1.65x0.55 smd: 1(-6.1,4) 2(-6.1,3.2) 3(-6.1,2.4) 4(-6.1,1.6) 5(-6.1,0.8) 6(-6.1,0) 7(-6.1,-0.8) 8(-6.1,-1.6) 9(-6.1,-2.4) 10(-6.1,-3.2) 11(-6.1,-4) 23(6.1,-4) 24(6.1,-3.2) 25(6.1,-2.4) 26(6.1,-1.6) 27(6.1,-0.8) 28(6.1,0) 29(6.1,0.8) 30(6.1,1.6) 31(6.1,2.4) 32(6.1,3.2) 33(6.1,4)
  oval 0.55x1.65 smd: 12(-4,-6.1) 13(-3.2,-6.1) 14(-2.4,-6.1) 15(-1.6,-6.1) 16(-0.8,-6.1) 17(0,-6.1) 18(0.8,-6.1) 19(1.6,-6.1) 20(2.4,-6.1) 21(3.2,-6.1) 22(4,-6.1) 34(4,6.1) 35(3.2,6.1) 36(2.4,6.1) 37(1.6,6.1) 38(0.8,6.1) 39(0,6.1) 40(-0.8,6.1) 41(-1.6,6.1) 42(-2.4,6.1) 43(-3.2,6.1) 44(-4,6.1)
Top Overlay:
  circle w0.6: c-3.85,3.85 r0.3
  circle w0.25: c-6.1,4.825 r0.125
  lines w0.2: -4.85,-4.85 4.85,-4.85 4.85,4.85 -4.85,4.85 -4.85,-4.85
Mechanical 13:
  circle w0.1: c-4.1,4.1 r0.5
  lines w0.1: -5,-5 5,-5 5,5 -5,5 -5,-5
Mechanical 15:
  lines w0.1: -0.5,0 0.5,0 ; 0,-0.5 0,0.5 ; -7,-7 7,-7 7,7 -7,7 -7,-7
3D body: height 2.35, standoff 0, extent -5,-5 5,5

## PQG44_M [mm] "44-Pin Plastic Quad Flat Pack (PQG44) - Pb-Free, IPC Low Density"
height 2.35
pads (44):
  oval 2.25x0.6 smd: 1(-6.2,4) 2(-6.2,3.2) 3(-6.2,2.4) 4(-6.2,1.6) 5(-6.2,0.8) 6(-6.2,0) 7(-6.2,-0.8) 8(-6.2,-1.6) 9(-6.2,-2.4) 10(-6.2,-3.2) 11(-6.2,-4) 23(6.2,-4) 24(6.2,-3.2) 25(6.2,-2.4) 26(6.2,-1.6) 27(6.2,-0.8) 28(6.2,0) 29(6.2,0.8) 30(6.2,1.6) 31(6.2,2.4) 32(6.2,3.2) 33(6.2,4)
  oval 0.6x2.25 smd: 12(-4,-6.2) 13(-3.2,-6.2) 14(-2.4,-6.2) 15(-1.6,-6.2) 16(-0.8,-6.2) 17(0,-6.2) 18(0.8,-6.2) 19(1.6,-6.2) 20(2.4,-6.2) 21(3.2,-6.2) 22(4,-6.2) 34(4,6.2) 35(3.2,6.2) 36(2.4,6.2) 37(1.6,6.2) 38(0.8,6.2) 39(0,6.2) 40(-0.8,6.2) 41(-1.6,6.2) 42(-2.4,6.2) 43(-3.2,6.2) 44(-4,6.2)
Top Overlay:
  circle w0.6: c-3.65,3.65 r0.3
  circle w0.25: c-6.2,4.85 r0.125
  lines w0.2: -4.65,-4.65 4.65,-4.65 4.65,4.65 -4.65,4.65 -4.65,-4.65
Mechanical 13:
  circle w0.1: c-4.1,4.1 r0.5
  lines w0.1: -5,-5 5,-5 5,5 -5,5 -5,-5
Mechanical 15:
  lines w0.1: -0.5,0 0.5,0 ; 0,-0.5 0,0.5 ; -7.8,-7.8 7.8,-7.8 7.8,7.8 -7.8,7.8 -7.8,-7.8
3D body: height 2.35, standoff 0, extent -5,-5 5,5

## PQG44_N [mm] "44-Pin Plastic Quad Flat Pack (PQG44) - Pb-Free, IPC Medium Density"
height 2.35
pads (44):
  oval 1.95x0.55 smd: 1(-6.15,4) 2(-6.15,3.2) 3(-6.15,2.4) 4(-6.15,1.6) 5(-6.15,0.8) 6(-6.15,0) 7(-6.15,-0.8) 8(-6.15,-1.6) 9(-6.15,-2.4) 10(-6.15,-3.2) 11(-6.15,-4) 23(6.15,-4) 24(6.15,-3.2) 25(6.15,-2.4) 26(6.15,-1.6) 27(6.15,-0.8) 28(6.15,0) 29(6.15,0.8) 30(6.15,1.6) 31(6.15,2.4) 32(6.15,3.2) 33(6.15,4)
  oval 0.55x1.95 smd: 12(-4,-6.15) 13(-3.2,-6.15) 14(-2.4,-6.15) 15(-1.6,-6.15) 16(-0.8,-6.15) 17(0,-6.15) 18(0.8,-6.15) 19(1.6,-6.15) 20(2.4,-6.15) 21(3.2,-6.15) 22(4,-6.15) 34(4,6.15) 35(3.2,6.15) 36(2.4,6.15) 37(1.6,6.15) 38(0.8,6.15) 39(0,6.15) 40(-0.8,6.15) 41(-1.6,6.15) 42(-2.4,6.15) 43(-3.2,6.15) 44(-4,6.15)
Top Overlay:
  circle w0.25: c-6.15,4.825 r0.125
  circle w0.6: c-3.75,3.75 r0.3
  lines w0.2: -4.75,-4.75 -4.75,4.75 4.75,4.75 4.75,-4.75 -4.75,-4.75
Mechanical 13:
  circle w0.1: c-4.1,4.1 r0.5
  lines w0.1: -5,-5 -5,5 5,5 5,-5 -5,-5
Mechanical 15:
  lines w0.1: -0.5,0 0.5,0 ; 0,-0.5 0,0.5 ; -7.35,-7.35 -7.35,7.35 7.35,7.35 7.35,-7.35 -7.35,-7.35
3D body: height 2.35, standoff 0, extent -5,-5 5,5

## PQG160_L [mm] "160-Pin Plastic Quad Flat Pack (PQG160) - Pb-Free, IPC High Density"
height 4.1
pads (160):
  oval 1.65x0.45 smd: 1(-15.1,12.675) 2(-15.1,12.025) 3(-15.1,11.375) 4(-15.1,10.725) 5(-15.1,10.075) 6(-15.1,9.425) 7(-15.1,8.775) 8(-15.1,8.125) 9(-15.1,7.475) 10(-15.1,6.825) 11(-15.1,6.175) 12(-15.1,5.525) 13(-15.1,4.875) 14(-15.1,4.225) 15(-15.1,3.575) 16(-15.1,2.925) 17(-15.1,2.275) 18(-15.1,1.625) 19(-15.1,0.975) 20(-15.1,0.325) 21(-15.1,-0.325) 22(-15.1,-0.975) 23(-15.1,-1.625) 24(-15.1,-2.275) 25(-15.1,-2.925) 26(-15.1,-3.575) 27(-15.1,-4.225) 28(-15.1,-4.875) 29(-15.1,-5.525) 30(-15.1,-6.175) 31(-15.1,-6.825) 32(-15.1,-7.475) 33(-15.1,-8.125) 34(-15.1,-8.775) 35(-15.1,-9.425) 36(-15.1,-10.075) 37(-15.1,-10.725) 38(-15.1,-11.375) 39(-15.1,-12.025) 40(-15.1,-12.675) 81(15.1,-12.675) 82(15.1,-12.025) 83(15.1,-11.375) 84(15.1,-10.725) 85(15.1,-10.075) 86(15.1,-9.425) 87(15.1,-8.775) 88(15.1,-8.125) 89(15.1,-7.475) 90(15.1,-6.825) 91(15.1,-6.175) 92(15.1,-5.525) 93(15.1,-4.875) 94(15.1,-4.225) 95(15.1,-3.575) 96(15.1,-2.925) 97(15.1,-2.275) 98(15.1,-1.625) 99(15.1,-0.975) 100(15.1,-0.325) 101(15.1,0.325) 102(15.1,0.975) 103(15.1,1.625) 104(15.1,2.275) 105(15.1,2.925) 106(15.1,3.575) 107(15.1,4.225) 108(15.1,4.875) 109(15.1,5.525) 110(15.1,6.175) 111(15.1,6.825) 112(15.1,7.475) 113(15.1,8.125) 114(15.1,8.775) 115(15.1,9.425) 116(15.1,10.075) 117(15.1,10.725) 118(15.1,11.375) 119(15.1,12.025) 120(15.1,12.675)
  oval 0.45x1.65 smd: 41(-12.675,-15.1) 42(-12.025,-15.1) 43(-11.375,-15.1) 44(-10.725,-15.1) 45(-10.075,-15.1) 46(-9.425,-15.1) 47(-8.775,-15.1) 48(-8.125,-15.1) 49(-7.475,-15.1) 50(-6.825,-15.1) 51(-6.175,-15.1) 52(-5.525,-15.1) 53(-4.875,-15.1) 54(-4.225,-15.1) 55(-3.575,-15.1) 56(-2.925,-15.1) 57(-2.275,-15.1) 58(-1.625,-15.1) 59(-0.975,-15.1) 60(-0.325,-15.1) 61(0.325,-15.1) 62(0.975,-15.1) 63(1.625,-15.1) 64(2.275,-15.1) 65(2.925,-15.1) 66(3.575,-15.1) 67(4.225,-15.1) 68(4.875,-15.1) 69(5.525,-15.1) 70(6.175,-15.1) 71(6.825,-15.1) 72(7.475,-15.1) 73(8.125,-15.1) 74(8.775,-15.1) 75(9.425,-15.1) 76(10.075,-15.1) 77(10.725,-15.1) 78(11.375,-15.1) 79(12.025,-15.1) 80(12.675,-15.1) 121(12.675,15.1) 122(12.025,15.1) 123(11.375,15.1) 124(10.725,15.1) 125(10.075,15.1) 126(9.425,15.1) 127(8.775,15.1) 128(8.125,15.1) 129(7.475,15.1) 130(6.825,15.1) 131(6.175,15.1) 132(5.525,15.1) 133(4.875,15.1) 134(4.225,15.1) 135(3.575,15.1) 136(2.925,15.1) 137(2.275,15.1) 138(1.625,15.1) 139(0.975,15.1) 140(0.325,15.1) 141(-0.325,15.1) 142(-0.975,15.1) 143(-1.625,15.1) 144(-2.275,15.1) 145(-2.925,15.1) 146(-3.575,15.1) 147(-4.225,15.1) 148(-4.875,15.1) 149(-5.525,15.1) 150(-6.175,15.1) 151(-6.825,15.1) 152(-7.475,15.1) 153(-8.125,15.1) 154(-8.775,15.1) 155(-9.425,15.1) 156(-10.075,15.1) 157(-10.725,15.1) 158(-11.375,15.1) 159(-12.025,15.1) 160(-12.675,15.1)
Top Overlay:
  circle w0.6: c-12.85,12.85 r0.3
  circle w0.25: c-15.1,13.45 r0.125
  lines w0.2: -13.85,-13.85 13.85,-13.85 13.85,13.85 -13.85,13.85 -13.85,-13.85
Mechanical 13:
  circle w0.1: c-13.1,13.1 r0.5
  lines w0.1: -14,-14 14,-14 14,14 -14,14 -14,-14
Mechanical 15:
  lines w0.1: -0.5,0 0.5,0 ; 0,-0.5 0,0.5 ; -16,-16 16,-16 16,16 -16,16 -16,-16
3D body: height 4.1, standoff 0, extent -14,-14 14,14

## PQG160_M [mm] "160-Pin Plastic Quad Flat Pack (PQG160) - Pb-Free, IPC Low Density"
height 4.1
pads (160):
  oval 2.25x0.45 smd: 1(-15.2,12.675) 2(-15.2,12.025) 3(-15.2,11.375) 4(-15.2,10.725) 5(-15.2,10.075) 6(-15.2,9.425) 7(-15.2,8.775) 8(-15.2,8.125) 9(-15.2,7.475) 10(-15.2,6.825) 11(-15.2,6.175) 12(-15.2,5.525) 13(-15.2,4.875) 14(-15.2,4.225) 15(-15.2,3.575) 16(-15.2,2.925) 17(-15.2,2.275) 18(-15.2,1.625) 19(-15.2,0.975) 20(-15.2,0.325) 21(-15.2,-0.325) 22(-15.2,-0.975) 23(-15.2,-1.625) 24(-15.2,-2.275) 25(-15.2,-2.925) 26(-15.2,-3.575) 27(-15.2,-4.225) 28(-15.2,-4.875) 29(-15.2,-5.525) 30(-15.2,-6.175) 31(-15.2,-6.825) 32(-15.2,-7.475) 33(-15.2,-8.125) 34(-15.2,-8.775) 35(-15.2,-9.425) 36(-15.2,-10.075) 37(-15.2,-10.725) 38(-15.2,-11.375) 39(-15.2,-12.025) 40(-15.2,-12.675) 81(15.2,-12.675) 82(15.2,-12.025) 83(15.2,-11.375) 84(15.2,-10.725) 85(15.2,-10.075) 86(15.2,-9.425) 87(15.2,-8.775) 88(15.2,-8.125) 89(15.2,-7.475) 90(15.2,-6.825) 91(15.2,-6.175) 92(15.2,-5.525) 93(15.2,-4.875) 94(15.2,-4.225) 95(15.2,-3.575) 96(15.2,-2.925) 97(15.2,-2.275) 98(15.2,-1.625) 99(15.2,-0.975) 100(15.2,-0.325) 101(15.2,0.325) 102(15.2,0.975) 103(15.2,1.625) 104(15.2,2.275) 105(15.2,2.925) 106(15.2,3.575) 107(15.2,4.225) 108(15.2,4.875) 109(15.2,5.525) 110(15.2,6.175) 111(15.2,6.825) 112(15.2,7.475) 113(15.2,8.125) 114(15.2,8.775) 115(15.2,9.425) 116(15.2,10.075) 117(15.2,10.725) 118(15.2,11.375) 119(15.2,12.025) 120(15.2,12.675)
  oval 0.45x2.25 smd: 41(-12.675,-15.2) 42(-12.025,-15.2) 43(-11.375,-15.2) 44(-10.725,-15.2) 45(-10.075,-15.2) 46(-9.425,-15.2) 47(-8.775,-15.2) 48(-8.125,-15.2) 49(-7.475,-15.2) 50(-6.825,-15.2) 51(-6.175,-15.2) 52(-5.525,-15.2) 53(-4.875,-15.2) 54(-4.225,-15.2) 55(-3.575,-15.2) 56(-2.925,-15.2) 57(-2.275,-15.2) 58(-1.625,-15.2) 59(-0.975,-15.2) 60(-0.325,-15.2) 61(0.325,-15.2) 62(0.975,-15.2) 63(1.625,-15.2) 64(2.275,-15.2) 65(2.925,-15.2) 66(3.575,-15.2) 67(4.225,-15.2) 68(4.875,-15.2) 69(5.525,-15.2) 70(6.175,-15.2) 71(6.825,-15.2) 72(7.475,-15.2) 73(8.125,-15.2) 74(8.775,-15.2) 75(9.425,-15.2) 76(10.075,-15.2) 77(10.725,-15.2) 78(11.375,-15.2) 79(12.025,-15.2) 80(12.675,-15.2) 121(12.675,15.2) 122(12.025,15.2) 123(11.375,15.2) 124(10.725,15.2) 125(10.075,15.2) 126(9.425,15.2) 127(8.775,15.2) 128(8.125,15.2) 129(7.475,15.2) 130(6.825,15.2) 131(6.175,15.2) 132(5.525,15.2) 133(4.875,15.2) 134(4.225,15.2) 135(3.575,15.2) 136(2.925,15.2) 137(2.275,15.2) 138(1.625,15.2) 139(0.975,15.2) 140(0.325,15.2) 141(-0.325,15.2) 142(-0.975,15.2) 143(-1.625,15.2) 144(-2.275,15.2) 145(-2.925,15.2) 146(-3.575,15.2) 147(-4.225,15.2) 148(-4.875,15.2) 149(-5.525,15.2) 150(-6.175,15.2) 151(-6.825,15.2) 152(-7.475,15.2) 153(-8.125,15.2) 154(-8.775,15.2) 155(-9.425,15.2) 156(-10.075,15.2) 157(-10.725,15.2) 158(-11.375,15.2) 159(-12.025,15.2) 160(-12.675,15.2)
Top Overlay:
  circle w0.6: c-12.65,12.65 r0.3
  circle w0.25: c-15.2,13.45 r0.125
  lines w0.2: -13.65,-13.65 13.65,-13.65 13.65,13.65 -13.65,13.65 -13.65,-13.65
Mechanical 13:
  circle w0.1: c-13.1,13.1 r0.5
  lines w0.1: -14,-14 14,-14 14,14 -14,14 -14,-14
Mechanical 15:
  lines w0.1: -0.5,0 0.5,0 ; 0,-0.5 0,0.5 ; -16.8,-16.8 16.8,-16.8 16.8,16.8 -16.8,16.8 -16.8,-16.8
3D body: height 4.1, standoff 0, extent -14,-14 14,14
